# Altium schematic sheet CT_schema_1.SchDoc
size 609 x 519 mm
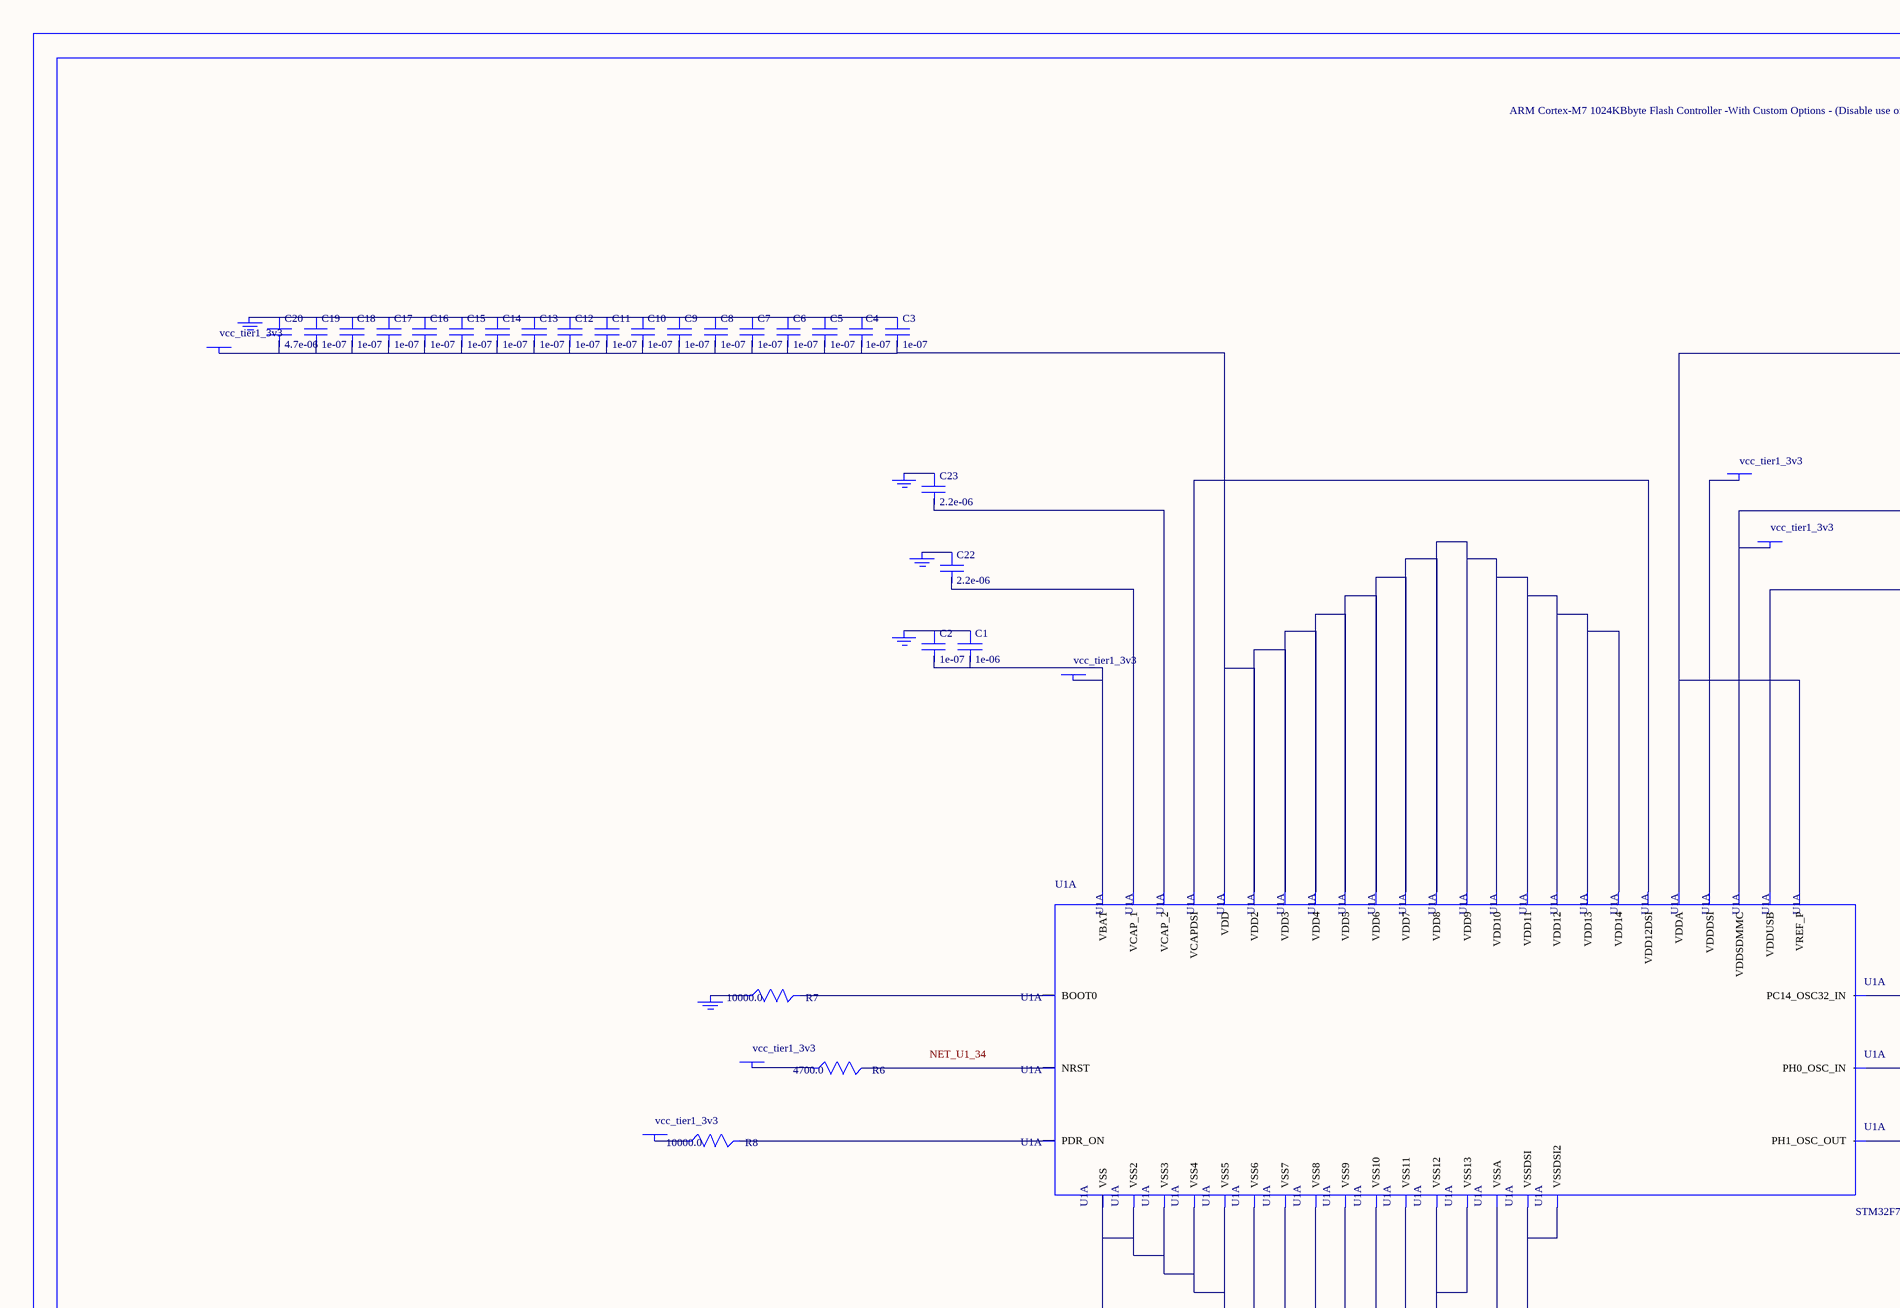
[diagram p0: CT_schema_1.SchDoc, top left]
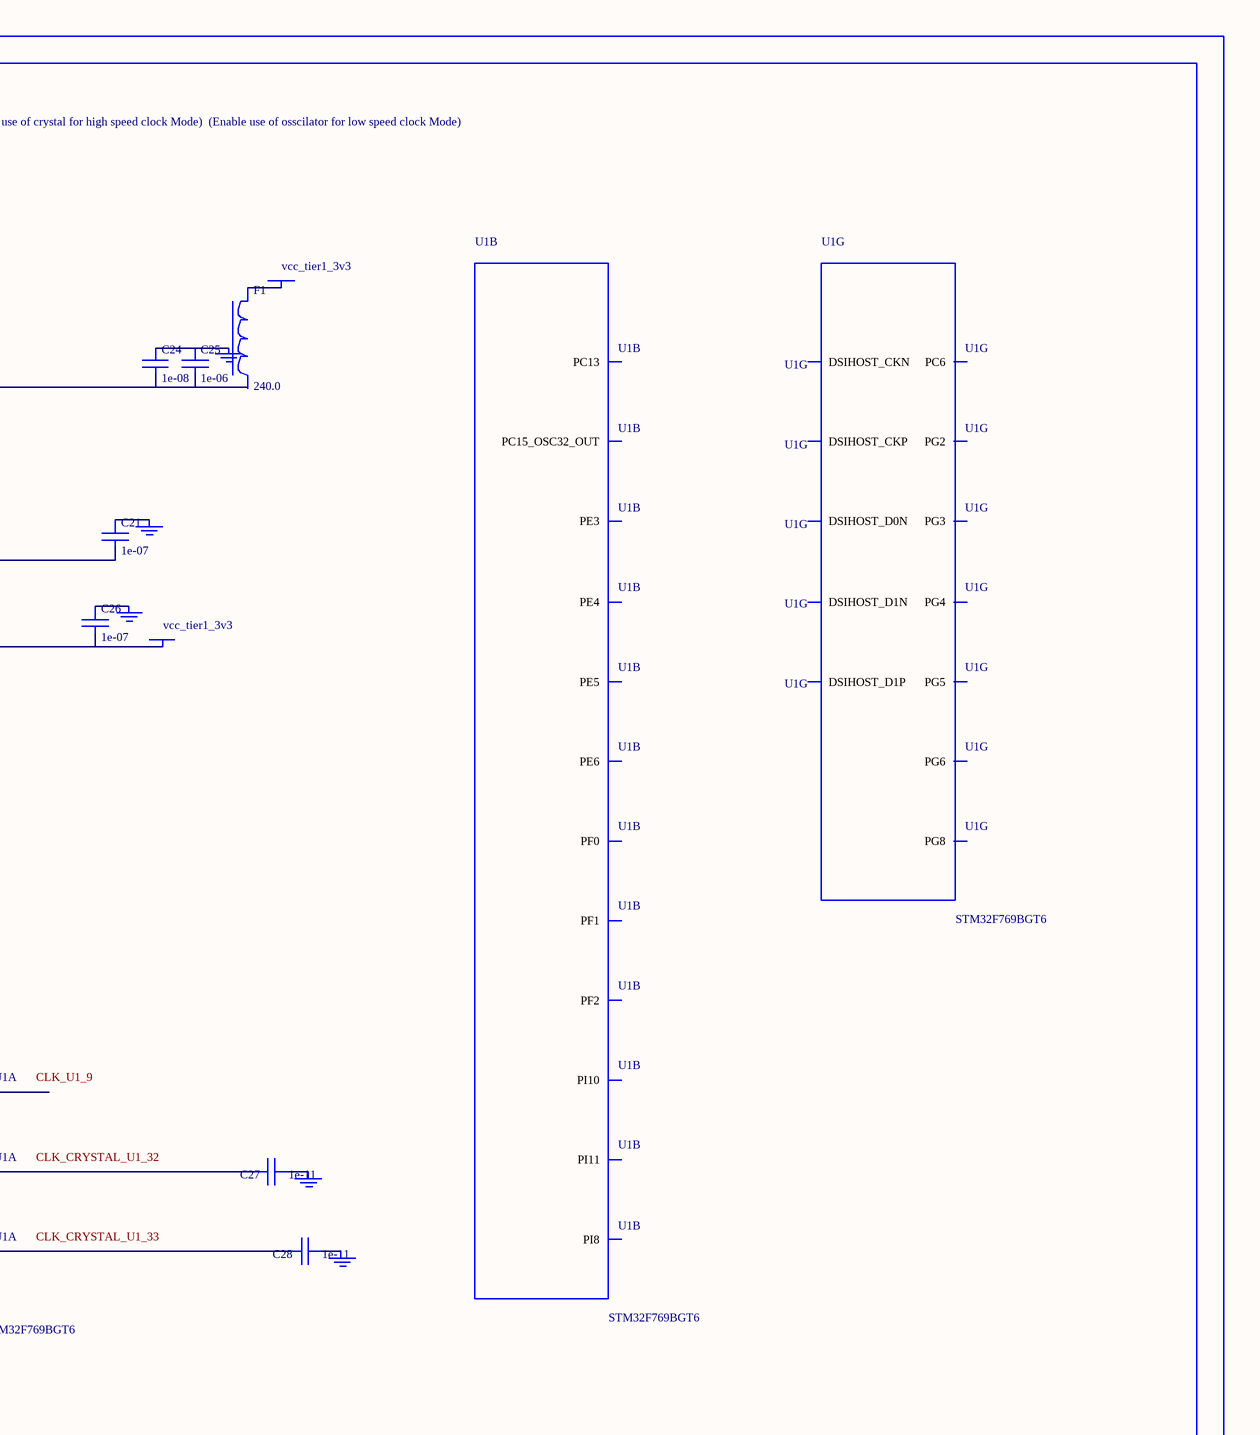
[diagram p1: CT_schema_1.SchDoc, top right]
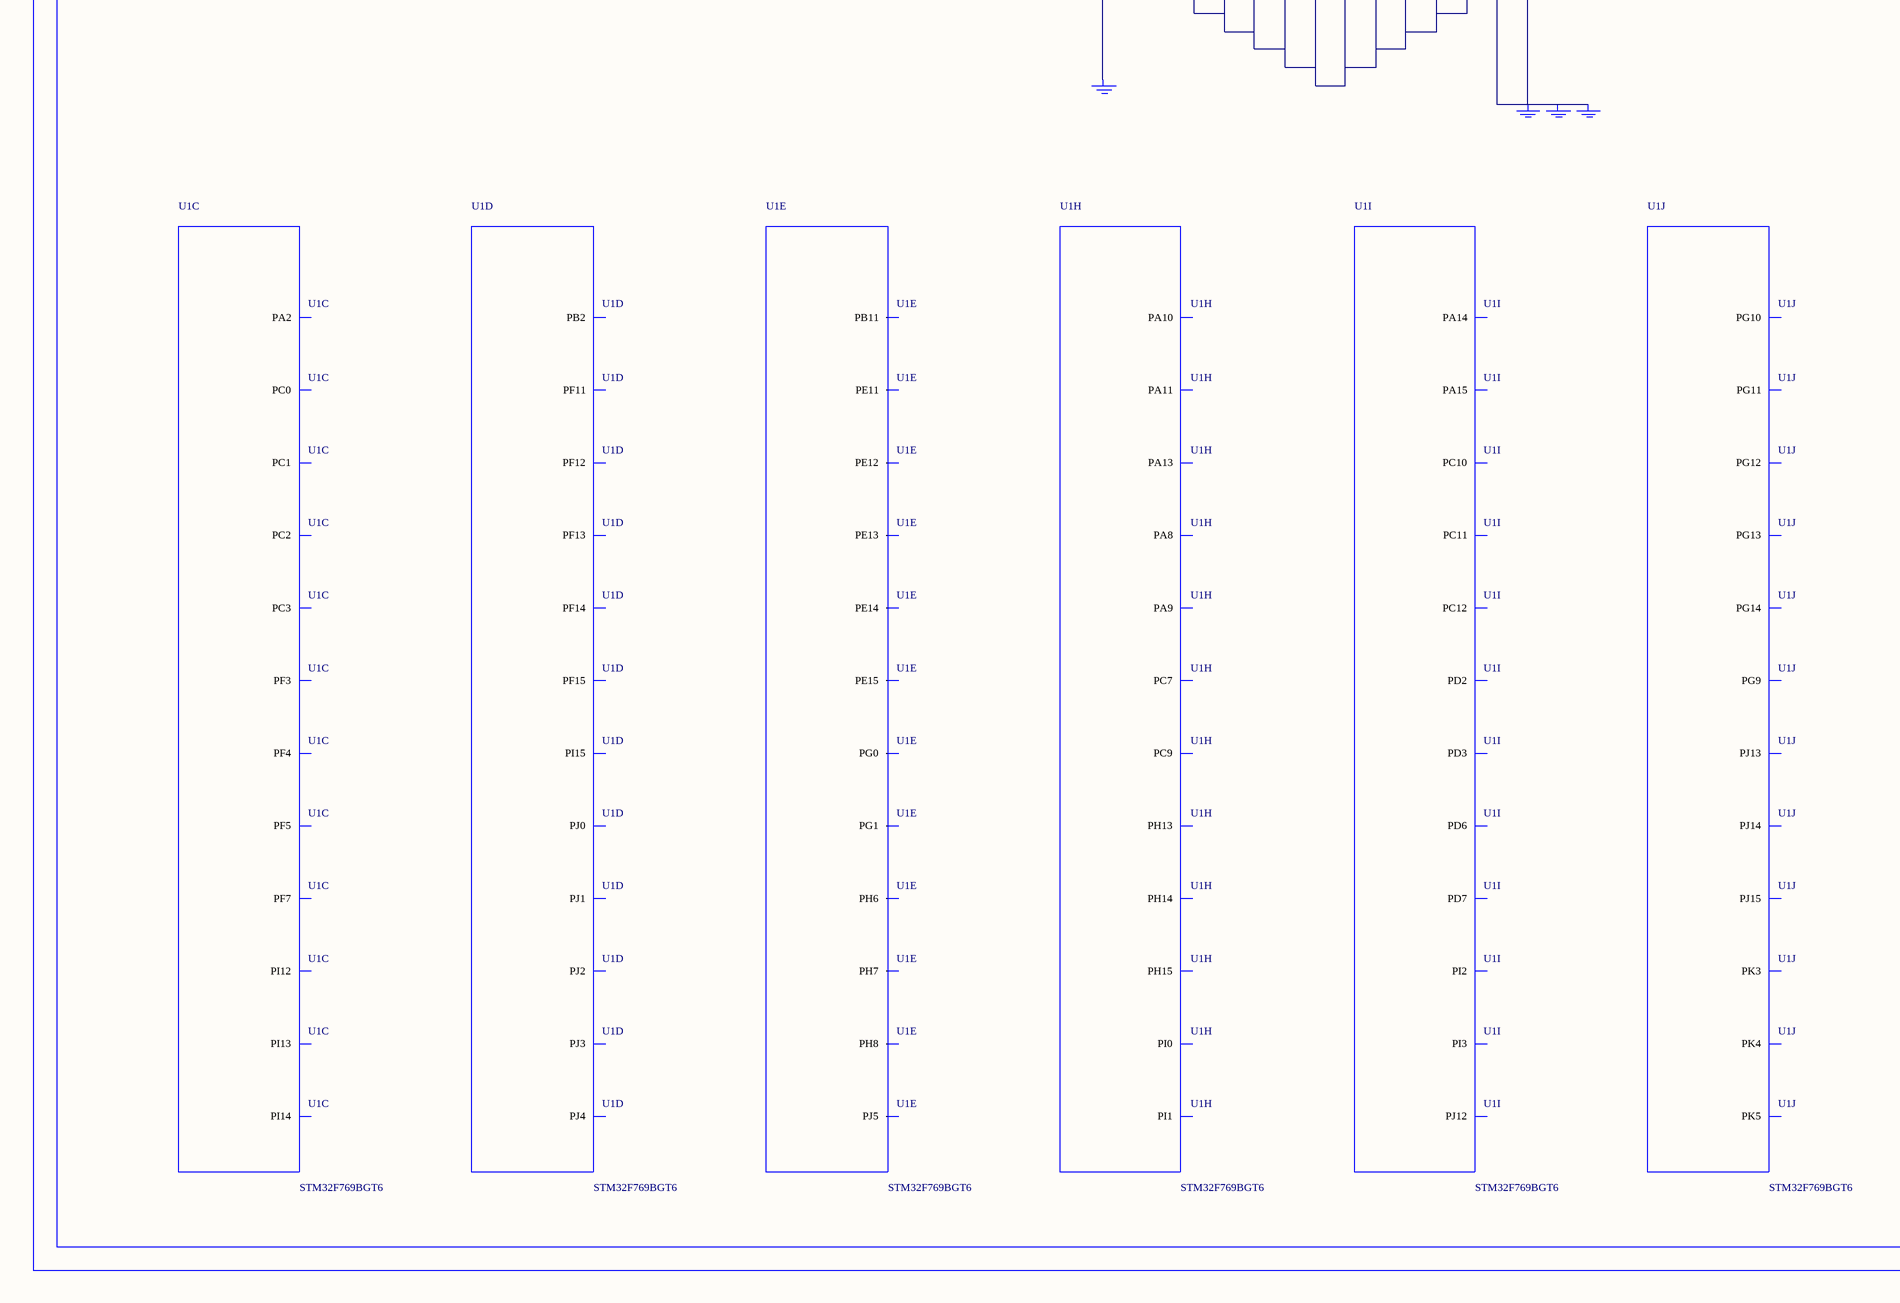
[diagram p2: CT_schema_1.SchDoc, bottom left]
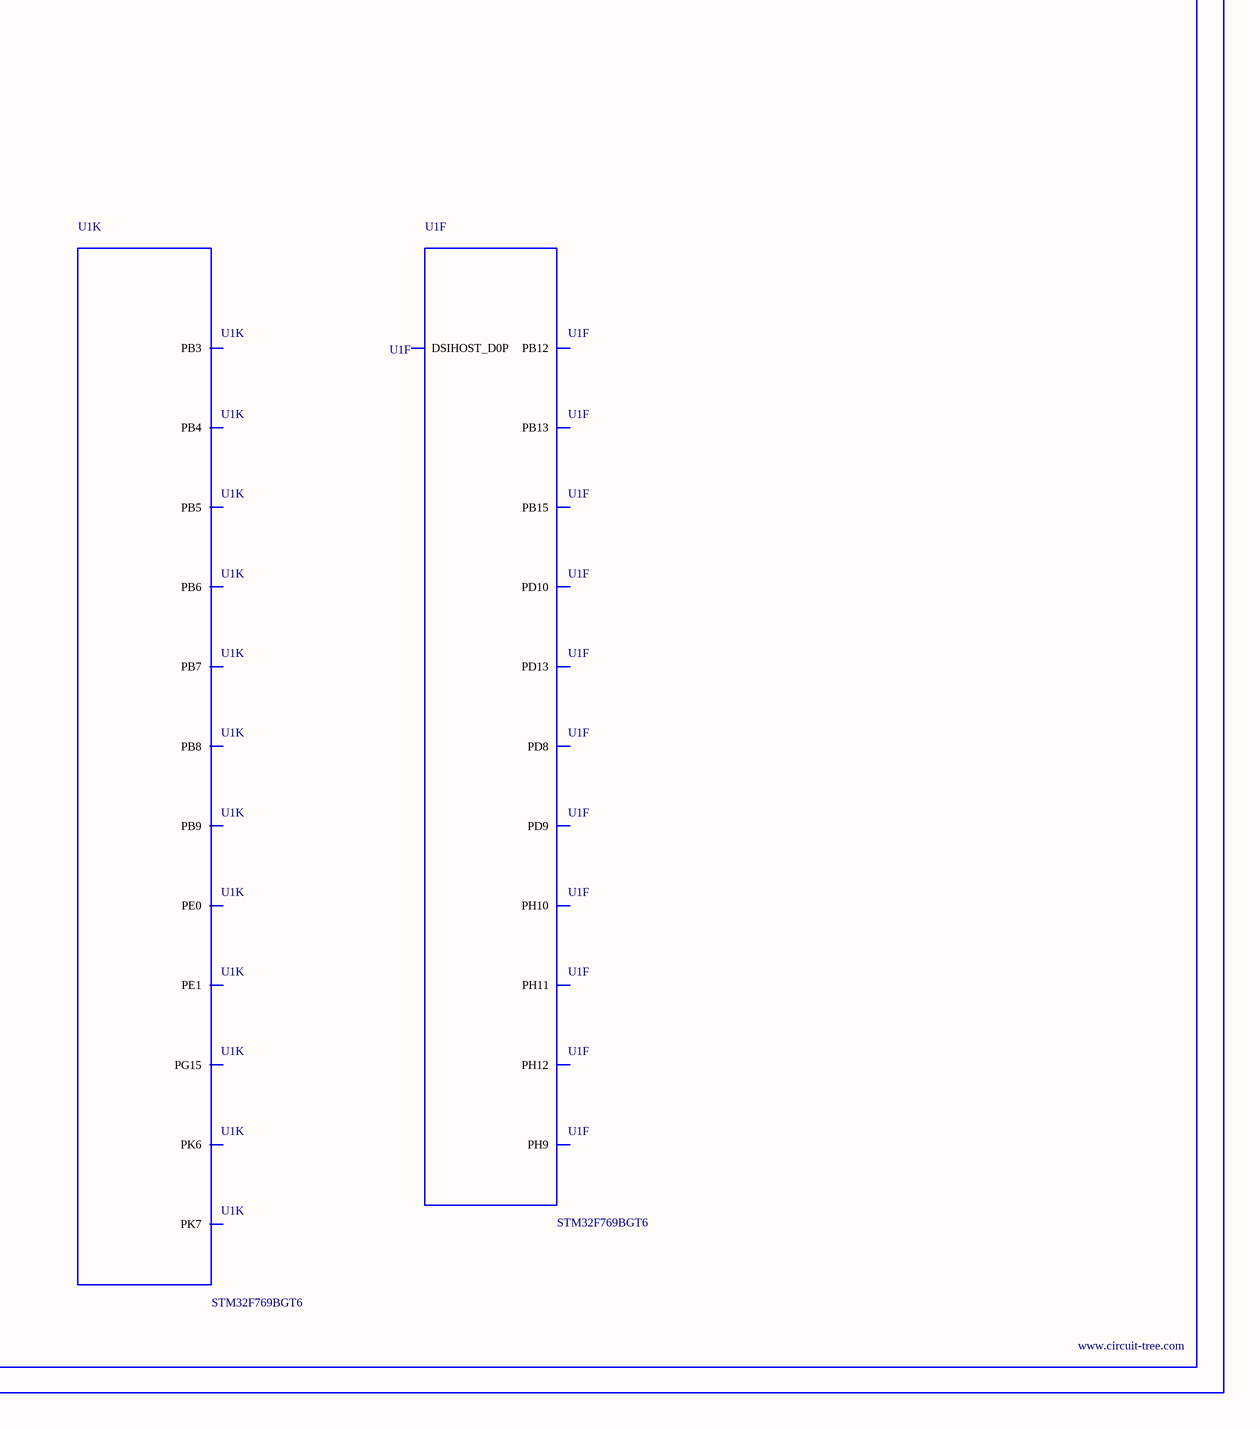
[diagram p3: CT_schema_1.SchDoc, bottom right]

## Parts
BORDER0  (no value)
C1  1e-06  [C0603]
C2  1e-07  [C0603]
C3  1e-07  [C0603]
C4  1e-07  [C0603]
C5  1e-07  [C0603]
C6  1e-07  [C0603]
C7  1e-07  [C0603]
C8  1e-07  [C0603]
C9  1e-07  [C0603]
C10  1e-07  [C0603]
C11  1e-07  [C0603]
C12  1e-07  [C0603]
C13  1e-07  [C0603]
C14  1e-07  [C0603]
C15  1e-07  [C0603]
C16  1e-07  [C0603]
C17  1e-07  [C0603]
C18  1e-07  [C0603]
C19  1e-07  [C0603]
C20  4.7e-06  [C0603]
C21  1e-07  [C0603]
C22  2.2e-06  [C0603]
C23  2.2e-06  [C0603]
C24  1e-08  [C0603]
C25  1e-06  [C0603]
C26  1e-07  [C0603]
C27  1e-11  [C0402]
C28  1e-11  [C0402]
F1  240.0  [L0603]
GND_INSTANCE_0_0  (no value)
GND_INSTANCE_0_1  (no value)
GND_INSTANCE_0_2  (no value)
GND_INSTANCE_0_3  (no value)
GND_INSTANCE_0_4  (no value)
GND_INSTANCE_0_5  (no value)
GND_INSTANCE_0_6  (no value)
GND_INSTANCE_0_7  (no value)
GND_INSTANCE_0_8  (no value)
GND_INSTANCE_0_9  (no value)
GND_INSTANCE_0_10  (no value)
GND_INSTANCE_0_11  (no value)
GND_INSTANCE_0_12  (no value)
GND_INSTANCE_0_13  (no value)
POWER_INSTANCE_0_0  vcc_tier1_3v3
POWER_INSTANCE_0_1  vcc_tier1_3v3
POWER_INSTANCE_0_2  vcc_tier1_3v3
POWER_INSTANCE_0_3  vcc_tier1_3v3
POWER_INSTANCE_0_4  vcc_tier1_3v3
POWER_INSTANCE_0_5  vcc_tier1_3v3
POWER_INSTANCE_0_6  vcc_tier1_3v3
POWER_INSTANCE_0_7  vcc_tier1_3v3
R6  4700.0  [R0603]
R7  10000.0  [R0603]
R8  10000.0  [R0603]
U1  STM32F769BGT6  [LQFP208]  (parts A,B,C,D,E,F,G,H,I,J,K of 17)

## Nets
NetC1_1: C1.1 C2.1 GND_INSTANCE_0_0.0(GND)
NetC1_2: C1.2 C2.2 POWER_INSTANCE_0_0.0(PWR) U1.6(VBAT)
NetC3_1: C3.1 C4.1 C5.1 C6.1 C7.1 C8.1 C9.1 C10.1 C11.1 C12.1 C13.1 C14.1 C15.1 C16.1 C17.1 C18.1 C19.1 C20.1 GND_INSTANCE_0_1.0(GND)
NetC3_2: C3.2 C4.2 C5.2 C6.2 C7.2 C8.2 C9.2 C10.2 C11.2 C12.2 C13.2 C14.2 C15.2 C16.2 C17.2 C18.2 C19.2 C20.2 POWER_INSTANCE_0_1.0(PWR) U1.15(VDD) U1.26(VDD2) U1.39(VDD3) U1.52(VDD4) U1.59(VDD5) U1.73(VDD6) U1.83(VDD7) U1.94(VDD8) U1.103(VDD9) U1.115(VDD10) U1.150(VDD11) U1.158(VDD12) U1.185(VDD13) U1.204(VDD14)
NetC21_1: C21.1 GND_INSTANCE_0_11.0(GND)
NetC21_2: C21.2 POWER_INSTANCE_0_5.0(PWR) U1.171(VDDSDMMC)
NetC22_1: C22.1 GND_INSTANCE_0_6.0(GND)
NetC22_2: C22.2 U1.92(VCAP_1)
NetC23_1: C23.1 GND_INSTANCE_0_10.0(GND)
NetC23_2: C23.2 U1.148(VCAP_2)
NetC24_1: C24.1 C25.1 GND_INSTANCE_0_5.0(GND)
NetC24_2: C24.2 C25.2 U1.41(VREF_P) U1.42(VDDA)
NetC26_1: C26.1 GND_INSTANCE_0_9.0(GND)
NetC26_2: C26.2 POWER_INSTANCE_0_4.0(PWR) U1.137(VDDUSB)
NetC27_1: C27.1 GND_INSTANCE_0_2.0(GND)
NetC27_2: C27.2 U1.32(PH0_OSC_IN)
NetC28_1: C28.1 GND_INSTANCE_0_3.0(GND)
NetC28_2: C28.2 U1.33(PH1_OSC_OUT)
NetF1_1: F1.1 POWER_INSTANCE_0_2.0(PWR)
NetGND_INSTANCE_0_4_0: GND_INSTANCE_0_4.0(GND) GND_INSTANCE_0_7.0(GND) GND_INSTANCE_0_8.0(GND) U1.40(VSSA) U1.122(VSSDSI) U1.128(VSSDSI2)
NetGND_INSTANCE_0_12_0: GND_INSTANCE_0_12.0(GND) R7.1
NetGND_INSTANCE_0_13_0: GND_INSTANCE_0_13.0(GND) U1.14(VSS) U1.25(VSS2) U1.51(VSS3) U1.60(VSS4) U1.72(VSS5) U1.82(VSS6) U1.93(VSS7) U1.114(VSS8) U1.136(VSS9) U1.149(VSS10) U1.170(VSS11) U1.184(VSS12) U1.202(VSS13)
NetPOWER_INSTANCE_0_3_0: POWER_INSTANCE_0_3.0(PWR) U1.118(VDDDSI)
NetPOWER_INSTANCE_0_6_0: POWER_INSTANCE_0_6.0(PWR) R8.1
NetPOWER_INSTANCE_0_7_0: POWER_INSTANCE_0_7.0(PWR) R6.1
NetR6_2: R6.2 U1.34(NRST)
NetR7_2: R7.2 U1.197(BOOT0)
NetR8_2: R8.2 U1.203(PDR_ON)
NetU1_119: U1.119(VCAPDSI) U1.125(VDD12DSI)

Not connected (* = marked no-connect by the designer): F1 2; U1 2(PE3) 3(PE4) 4(PE5) 5(PE6) 7(PI8) 8(PC13) 9(PC14_OSC32_IN) 10(PC15_OSC32_OUT) 12(PI10) 13(PI11) 16(PF0) 17(PF1) 18(PF2) 19(PI12) 20(PI13) 21(PI14) 22(PF3) 23(PF4) 24(PF5) 28(PF7) 35(PC0) 36(PC1) 37(PC2) 38(PC3) 45(PA2) 63(PB2) 64(PI15) 65(PJ0) 66(PJ1) 67(PJ2) 68(PJ3) 69(PJ4) 70(PF11) 71(PF12) 74(PF13) 75(PF14) 76(PF15) 77(PG0) 78(PG1) 85(PE11) 86(PE12) 87(PE13) 88(PE14) 89(PE15) 91(PB11) 95(PJ5) 96(PH6) 97(PH7) 98(PH8) 99(PH9) 100(PH10) 101(PH11) 102(PH12) 104(PB12) 105(PB13) 107(PB15) 108(PD8) 109(PD9) 110(PD10) 113(PD13) 120(DSIHOST_D0P) 121(DSIHOST_D0N) 123(DSIHOST_CKP) 124(DSIHOST_CKN) 126(DSIHOST_D1P) 127(DSIHOST_D1N) 129(PG2) 130(PG3) 131(PG4) 132(PG5) 133(PG6) 135(PG8) 138(PC6) 139(PC7) 141(PC9) 142(PA8) 143(PA9) 144(PA10) 145(PA11) 147(PA13) 151(PH13) 152(PH14) 153(PH15) 154(PI0) 155(PI1) 156(PI2) 157(PI3) 159(PA14) 160(PA15) 161(PC10) 162(PC11) 163(PC12) 166(PD2) 167(PD3) 172(PD6) 173(PD7) 174(PJ12) 175(PJ13) 176(PJ14) 177(PJ15) 178(PG9) 179(PG10) 180(PG11) 181(PG12) 182(PG13) 183(PG14) 186(PK3) 187(PK4) 188(PK5) 189(PK6) 190(PK7) 191(PG15) 192(PB3) 193(PB4) 194(PB5) 195(PB6) 196(PB7) 198(PB8) 199(PB9) 200(PE0) 201(PE1)

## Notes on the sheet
- Labels drawn without touching a wire or pin: CLK_CRYSTAL_U1_32, CLK_CRYSTAL_U1_33, CLK_U1_9, NET_U1_34

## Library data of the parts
BORDER0 = BORDER_PAGE0
C1 C25 = C0603C105K3RACTU
C2-C19 C21 C26 = 06035C104K4Z2A
C20 = GRM188R6YA475KE15D
C22 C23 = C0603C225K8RACTU
C24 = 06035C103K4Z2A
C27 C28 = C0402C100K3GACTU
F1 = Z0603C241ASMST
GND_INSTANCE_0_0-GND_INSTANCE_0_13 = GND
POWER_INSTANCE_0_0-POWER_INSTANCE_0_7 = PWR
R6 = RC0603JR-074K7L
R7 R8 = RC0603JR-0710KL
